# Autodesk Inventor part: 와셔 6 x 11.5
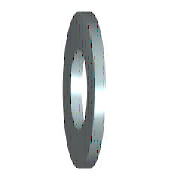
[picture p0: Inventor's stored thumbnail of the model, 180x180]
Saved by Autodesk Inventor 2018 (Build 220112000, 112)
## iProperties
IsCustomPart: 1
Created: 2012-02
Part Number: 와셔 6 x 11.5
Material: 강철, 연강
Description: 평면 와셔
Document SubType Name: Modeling
Standard: KS B 1326
Designer: mduedu
Standards Organization: KS
Language: ko-KR
Size Designation: 6x11.5
Categories: <MemberInstance><Categories><Category DisplayName="조임쇠" InternalName="e4da775c-781d-43d5-af7c-5136215cf5a6" Mnemonic="FSTN"><Category DisplayName="와셔" InternalN
Density: 7.86 g/cm^3
Mass: 0.901687 g
Surface Area: 2.33373 cm^2
Volume: 0.114718 cm^3
Appearance: 주황색
Author: mduedu
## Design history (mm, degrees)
sketch "스케치"
  geometry: C1 r 5.75 at (0, 0); C2 r 3.2 at (0, 0); 1 further point
  constraints: 2 centre point, 2 coincident
  dimensions: "d0" = 6.4 diameter of C2 (= SD1); "d1" = 11.5 diameter of C1 (= SD2)
extrude "본체" new body sketch "스케치" distance "d2" = 1.6 (= SD); taper "d3" = 0 deg
workaxis "Work Axis1"
workplane "Work Plane1"
body "Solid1"
other parameters: "SD1" = 6.4 [user parameter; used in 1 equation term], "SD2" = 11.5 [user parameter; used in 1 equation term], "SD" = 1.6 [user parameter; used in 1 equation term], "d4" = 0, "d5" = 0, "d6" = 0, "d7" = 0, "NND" = 6 [user parameter]
